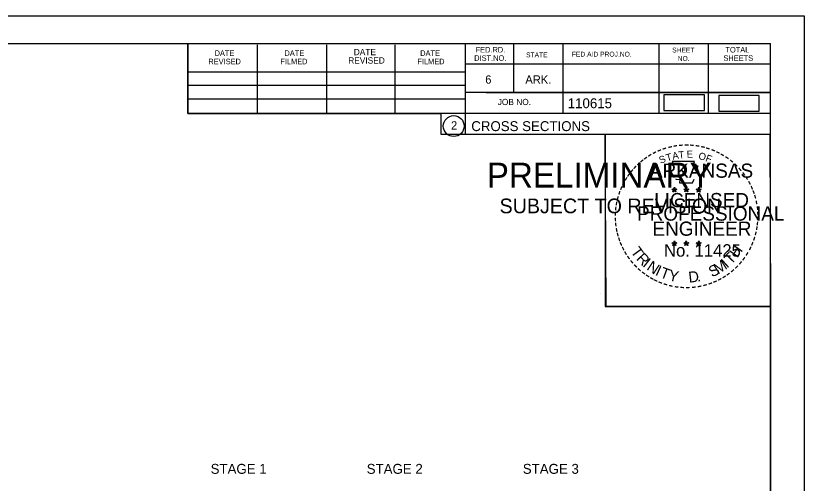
# Model space of a CAD drawing. Extents: x 1372132 to 1372465, y 380083 to 381790.
# Drawn here: x 1372353.7 to 1372464.9, y 381297.6 to 381363.5 of the extents above; entities that cross this region are included whole.
import ezdxf

# ---------------------------------------------------------------- set-up
doc = ezdxf.new("R2010")
doc.units = 0
for name, color, linetype in [('R_Axis Annot', 7, 'Continuous'), ('R_Border', 7, 'Continuous'), ('R_Border PE', 7, 'Continuous'), ('R_Border Prem', 7, 'Continuous'), ('R_Erosion', 7, 'Continuous'), ('R_No Plot', 7, 'Continuous')]:
    doc.layers.add(name, color=color, linetype=linetype)

msp = doc.modelspace()

# ---------------------------------------------------------------- linework, layer by layer
at = {"layer": 'R_Border'}
for p, q in [((1372144.01, 381359.62), (1372460.19, 381359.62)), ((1372377.93, 381349.74), (1372377.93, 381359.62)), ((1372387.79, 381349.74), (1372387.79, 381359.42)), ((1372397.55, 381349.74), (1372397.55, 381359.42)), ((1372407.23, 381349.74), (1372407.23, 381359.42)), ((1372417.09, 381359.62), (1372417.09, 381346.82)), ((1372423.93, 381359.62), (1372423.93, 381352.68)), ((1372430.87, 381359.62), (1372430.87, 381349.74)), ((1372444.45, 381359.62), (1372444.45, 381349.74)), ((1372451.39, 381359.62), (1372451.39, 381349.74)), ((1372460.19, 381154.16), (1372460.19, 381359.62)), ((1372460.19, 381356.68), (1372417.09, 381356.68)), ((1372460.19, 381356.7), (1372460.19, 381356.7)), ((1372377.93, 381355.6), (1372417.09, 381355.6)), ((1372377.93, 381353.74), (1372417.09, 381353.74)), ((1372460.19, 381352.68), (1372417.09, 381352.68)), ((1372420.05, 381352.68), (1372460.19, 381352.68)), ((1372377.93, 381349.74), (1372377.93, 381351.8)), ((1372377.93, 381351.8), (1372417.09, 381351.8)), ((1372460.19, 381349.74), (1372377.93, 381349.74)), ((1372417.09, 381346.82), (1372460.19, 381346.82))]:
    msp.add_line(p, q, dxfattribs=at)
msp.add_circle((1372415.48, 381347.96), 1.47, dxfattribs=at)
at = {"layer": 'R_Border PE'}
for p, q in [((1372446.28, 381339.08), (1372446.63, 381338.97)), ((1372446.28, 381339.08), (1372446.53, 381339.03)), ((1372446.28, 381339.08), (1372446.52, 381338.96)), ((1372446.41, 381338.67), (1372446.63, 381338.97)), ((1372446.41, 381338.67), (1372446.54, 381338.91)), ((1372446.41, 381338.67), (1372446.63, 381338.89)), ((1372446.63, 381339.33), (1372446.59, 381339.08)), ((1372446.63, 381338.97), (1372446.63, 381339.33)), ((1372446.63, 381339.33), (1372446.68, 381339.08)), ((1372446.98, 381339.08), (1372446.63, 381338.97)), ((1372446.84, 381338.67), (1372446.63, 381338.97)), ((1372446.84, 381338.67), (1372446.63, 381338.88)), ((1372446.98, 381339.08), (1372446.69, 381339.03)), ((1372446.84, 381338.67), (1372446.7, 381338.96)), ((1372446.98, 381339.08), (1372446.77, 381338.98)), ((1372447.95, 381339.08), (1372448.3, 381338.97)), ((1372447.95, 381339.08), (1372448.2, 381339.03)), ((1372447.95, 381339.08), (1372448.19, 381338.96)), ((1372448.08, 381338.67), (1372448.3, 381338.97)), ((1372448.08, 381338.67), (1372448.21, 381338.91)), ((1372448.08, 381338.67), (1372448.3, 381338.89)), ((1372448.3, 381339.33), (1372448.26, 381339.08)), ((1372448.3, 381338.97), (1372448.3, 381339.33)), ((1372448.3, 381339.33), (1372448.35, 381339.08)), ((1372448.65, 381339.08), (1372448.3, 381338.97)), ((1372448.51, 381338.67), (1372448.3, 381338.97)), ((1372448.51, 381338.67), (1372448.3, 381338.88)), ((1372448.65, 381339.08), (1372448.36, 381339.03)), ((1372448.51, 381338.67), (1372448.37, 381338.96)), ((1372448.65, 381339.08), (1372448.44, 381338.98)), ((1372449.71, 381339.07), (1372450.06, 381338.96)), ((1372449.71, 381339.07), (1372449.97, 381339.02)), ((1372449.71, 381339.07), (1372449.95, 381338.94)), ((1372449.85, 381338.66), (1372450.06, 381338.96)), ((1372449.85, 381338.66), (1372449.97, 381338.9)), ((1372449.85, 381338.66), (1372450.06, 381338.88)), ((1372450.06, 381339.32), (1372450.02, 381339.07)), ((1372450.06, 381338.96), (1372450.06, 381339.32)), ((1372450.06, 381339.32), (1372450.11, 381339.07)), ((1372450.41, 381339.07), (1372450.06, 381338.96)), ((1372450.28, 381338.66), (1372450.06, 381338.96)), ((1372450.28, 381338.66), (1372450.06, 381338.87)), ((1372450.41, 381339.07), (1372450.12, 381339.02)), ((1372450.28, 381338.66), (1372450.14, 381338.95)), ((1372450.41, 381339.07), (1372450.21, 381338.96)), ((1372446.28, 381331.51), (1372446.62, 381331.39)), ((1372446.28, 381331.51), (1372446.53, 381331.46)), ((1372446.28, 381331.51), (1372446.51, 381331.38)), ((1372446.41, 381331.1), (1372446.62, 381331.39)), ((1372446.41, 381331.1), (1372446.53, 381331.34)), ((1372446.41, 381331.1), (1372446.62, 381331.31)), ((1372446.62, 381331.76), (1372446.58, 381331.51)), ((1372446.62, 381331.39), (1372446.62, 381331.76)), ((1372446.62, 381331.76), (1372446.67, 381331.51)), ((1372446.97, 381331.51), (1372446.62, 381331.39)), ((1372446.84, 381331.1), (1372446.62, 381331.39)), ((1372446.84, 381331.1), (1372446.62, 381331.31)), ((1372446.97, 381331.51), (1372446.69, 381331.46)), ((1372446.84, 381331.1), (1372446.7, 381331.39)), ((1372446.97, 381331.51), (1372446.77, 381331.4)), ((1372447.94, 381331.51), (1372448.29, 381331.39)), ((1372447.94, 381331.51), (1372448.2, 381331.46)), ((1372447.94, 381331.51), (1372448.18, 381331.38)), ((1372448.08, 381331.1), (1372448.29, 381331.39)), ((1372448.08, 381331.1), (1372448.2, 381331.34)), ((1372448.08, 381331.1), (1372448.29, 381331.31)), ((1372448.29, 381331.76), (1372448.25, 381331.51)), ((1372448.29, 381331.39), (1372448.29, 381331.76)), ((1372448.29, 381331.76), (1372448.34, 381331.51)), ((1372448.64, 381331.51), (1372448.29, 381331.39)), ((1372448.51, 381331.1), (1372448.29, 381331.39)), ((1372448.51, 381331.1), (1372448.29, 381331.31)), ((1372448.64, 381331.51), (1372448.35, 381331.46)), ((1372448.51, 381331.1), (1372448.37, 381331.39)), ((1372448.64, 381331.51), (1372448.44, 381331.4)), ((1372449.71, 381331.5), (1372450.06, 381331.38)), ((1372449.71, 381331.5), (1372449.96, 381331.45)), ((1372449.71, 381331.5), (1372449.95, 381331.37)), ((1372449.84, 381331.09), (1372450.06, 381331.38)), ((1372449.84, 381331.09), (1372449.97, 381331.33)), ((1372449.84, 381331.09), (1372450.06, 381331.3)), ((1372450.06, 381331.75), (1372450.02, 381331.5)), ((1372450.06, 381331.38), (1372450.06, 381331.75)), ((1372450.06, 381331.75), (1372450.11, 381331.5)), ((1372450.41, 381331.5), (1372450.06, 381331.38)), ((1372450.27, 381331.09), (1372450.06, 381331.38)), ((1372450.27, 381331.09), (1372450.06, 381331.3)), ((1372450.41, 381331.5), (1372450.12, 381331.45)), ((1372450.27, 381331.09), (1372450.14, 381331.38)), ((1372450.41, 381331.5), (1372450.2, 381331.39))]:
    msp.add_line(p, q, dxfattribs=at)
for points in [[(1372446.32, 381342.96), (1372446.59, 381342.13)], [(1372449.83, 381342.03), (1372449.97, 381342.32), (1372449.29, 381342.29), (1372449.44, 381342.96), (1372446.32, 381342.96)], [(1372446.81, 381340.53), (1372446.81, 381340.45), (1372447.38, 381340.43), (1372447.32, 381339.95), (1372449.19, 381339.95), (1372449.39, 381340.49)], [(1372446.63, 381339.33), (1372446.84, 381338.67), (1372446.28, 381339.08), (1372446.98, 381339.08), (1372446.41, 381338.67), (1372446.63, 381339.33)], [(1372448.3, 381339.33), (1372448.51, 381338.67), (1372447.95, 381339.08), (1372448.65, 381339.08), (1372448.08, 381338.67), (1372448.3, 381339.33)], [(1372450.06, 381339.32), (1372450.28, 381338.66), (1372449.71, 381339.07), (1372450.41, 381339.07), (1372449.85, 381338.66), (1372450.06, 381339.32)], [(1372446.62, 381331.76), (1372446.84, 381331.1), (1372446.28, 381331.51), (1372446.97, 381331.51), (1372446.41, 381331.1), (1372446.62, 381331.76)], [(1372448.29, 381331.76), (1372448.51, 381331.1), (1372447.94, 381331.51), (1372448.64, 381331.51), (1372448.08, 381331.1), (1372448.29, 381331.76)], [(1372450.06, 381331.75), (1372450.27, 381331.09), (1372449.71, 381331.5), (1372450.41, 381331.5), (1372449.84, 381331.09), (1372450.06, 381331.75)]]:
    msp.add_lwpolyline(points, dxfattribs=at)
for centre, radius in [((1372446.63, 381338.97), 0.172), ((1372446.63, 381338.97), 0.145), ((1372446.63, 381338.97), 0.116), ((1372446.63, 381338.97), 0.0991), ((1372446.63, 381338.97), 0.0747), ((1372446.63, 381338.97), 0.0495), ((1372446.63, 381338.97), 0.0296), ((1372448.3, 381338.97), 0.172), ((1372448.3, 381338.97), 0.145), ((1372448.3, 381338.97), 0.116), ((1372448.3, 381338.97), 0.0991), ((1372448.3, 381338.97), 0.0747), ((1372448.3, 381338.97), 0.0495), ((1372448.3, 381338.97), 0.0296), ((1372450.06, 381338.95), 0.172), ((1372450.06, 381338.95), 0.145), ((1372450.06, 381338.95), 0.116), ((1372450.06, 381338.95), 0.0991), ((1372450.06, 381338.95), 0.0747), ((1372450.06, 381338.95), 0.0495), ((1372450.06, 381338.95), 0.0296), ((1372446.62, 381331.39), 0.172), ((1372446.62, 381331.39), 0.145), ((1372446.62, 381331.39), 0.116), ((1372446.62, 381331.39), 0.0991), ((1372446.62, 381331.39), 0.0747), ((1372446.62, 381331.39), 0.0495), ((1372446.62, 381331.39), 0.0296), ((1372448.29, 381331.39), 0.172), ((1372448.29, 381331.39), 0.145), ((1372448.29, 381331.39), 0.116), ((1372448.29, 381331.39), 0.0991), ((1372448.29, 381331.39), 0.0747), ((1372448.29, 381331.39), 0.0495), ((1372448.29, 381331.39), 0.0296), ((1372450.06, 381331.38), 0.172), ((1372450.06, 381331.38), 0.145), ((1372450.06, 381331.38), 0.116), ((1372450.06, 381331.38), 0.0991), ((1372450.06, 381331.38), 0.0747), ((1372450.06, 381331.38), 0.0495), ((1372450.06, 381331.38), 0.0296)]:
    msp.add_circle(centre, radius, dxfattribs=at)
at = {"layer": 'R_Erosion'}
for points in [[(1372445.13, 381350.17), (1372450.85, 381350.17), (1372450.85, 381352.36), (1372445.13, 381352.36)], [(1372452.88, 381350.08), (1372458.59, 381350.08), (1372458.59, 381352.27), (1372452.88, 381352.27)]]:
    msp.add_lwpolyline(points, close=True, dxfattribs=at)
at = {"layer": 'R_No Plot'}
for p, q in [((1372131.61, 381363.52), (1372464.95, 381363.52)), ((1372436.23, 381324.37), (1372436.23, 381324.37))]:
    msp.add_line(p, q, dxfattribs=at)
for points in [[(1372131.61, 381363.52), (1372464.95, 381363.52), (1372464.95, 381150.18), (1372131.61, 381150.18)], [(1372377.93, 381359.62), (1372377.93, 381349.74), (1372413.67, 381349.74), (1372413.67, 381346.82), (1372436.87, 381346.82), (1372436.87, 381322.49), (1372460.19, 381322.49), (1372460.19, 381154.16), (1372144.01, 381154.16), (1372144.01, 381359.62)], [(1372436.87, 381346.82), (1372460.07, 381346.82), (1372460.19, 381322.49), (1372436.99, 381322.49)]]:
    msp.add_lwpolyline(points, close=True, dxfattribs=at)

# ---------------------------------------------------------------- texts
at = {"layer": 'R_Axis Annot'}
for s, p in [('STAGE 1', (1372381.17, 381298.91)), ('STAGE 2', (1372403.2, 381298.91)), ('STAGE 3', (1372425.23, 381298.91))]:
    msp.add_text(s, height=1.4, dxfattribs=at).set_placement(p)
at = {"layer": 'R_Border'}
for s, height, p in [('DATE', 0.879, (1372401.37, 381357.96)), ('FED.RD.', 0.782, (1372418.57, 381358.34)), ('SHEET', 0.684, (1372446.31, 381358.34)), ('TOTAL', 0.782, (1372453.83, 381358.34)), ('DATE', 0.782, (1372381.73, 381357.86)), ('DATE', 0.782, (1372391.59, 381357.86)), ('DATE', 0.782, (1372410.75, 381357.86)), ('DIST.NO.', 0.782, (1372418.37, 381357.16)), ('STATE', 0.684, (1372425.69, 381357.66)), ('FED.AID PROJ.NO.', 0.684, (1372432.15, 381357.76)), ('NO.', 0.684, (1372447.09, 381357.16)), ('SHEETS', 0.782, (1372453.55, 381357.16)), ('REVISED', 0.782, (1372380.85, 381356.68)), ('FILMED', 0.782, (1372391.01, 381356.68)), ('REVISED', 0.879, (1372400.59, 381356.78)), ('FILMED', 0.782, (1372410.35, 381356.68)), ('6', 1.17, (1372419.93, 381353.94)), ('ARK.', 1.172, (1372425.59, 381353.94)), ('JOB NO.', 0.879, (1372421.69, 381350.92)), ('110615', 1.4, (1372431.57, 381350.48)), ('2', 1.17, (1372415.1, 381347.47)), ('CROSS SECTIONS', 1.4, (1372417.96, 381347.25))]:
    msp.add_text(s, height=height, rotation=360, dxfattribs=at).set_placement(p)
at = {"layer": 'R_Border PE'}
for s, height, rotation, p in [('-', 1.6, 28.7918, (1372443.8, 381343.5)), ('-', 1.6, 24.3072, (1372444.43, 381343.81)), ('-', 1.6, 19.1761, (1372445.07, 381344.08)), ('-', 1.6, 13.6301, (1372445.82, 381344.32)), ('-', 1.6, 10.2193, (1372446.5, 381344.49)), ('T', 1, 6.0228, (1372447.26, 381343.38)), ('-', 1.6, 5.8968, (1372447.23, 381344.6)), ('-', 1.6, 0.1862, (1372448, 381344.67)), ('E', 1, 0.8323, (1372448.37, 381343.49)), ('-', 1.6, 357.743, (1372448.72, 381344.66)), ('-', 1.6, 352.1617, (1372449.46, 381344.6)), ('-', 1.6, 347.2049, (1372450.18, 381344.49)), ('-', 1.6, 342.3362, (1372450.82, 381344.33)), ('-', 1.6, 337.8551, (1372451.55, 381344.11)), ('-', 1.6, 334.1211, (1372452.18, 381343.84)), ('-', 1.6, 38.9507, (1372442.15, 381342.35)), ('-', 1.6, 36.2317, (1372442.63, 381342.73)), ('-', 1.6, 34.0636, (1372443.2, 381343.13)), ('S', 1, 21.594, (1372444.68, 381342.63)), ('T', 1, 16.4036, (1372445.59, 381342.97)), ('A', 1, 11.2132, (1372446.42, 381343.22)), ('O', 1, 350.4515, (1372449.97, 381343.28)), ('F', 1, 340.0707, (1372450.93, 381343.05)), ('-', 1.6, 329.6409, (1372452.76, 381343.55)), ('-', 1.6, 325.8627, (1372453.41, 381343.19)), ('-', 1.6, 320.5297, (1372454.02, 381342.77)), ('-', 1.6, 48.423, (1372441.27, 381341.46)), ('-', 1.6, 42.9622, (1372441.72, 381341.94)), ('ARKANSAS', 2, 360, (1372443.17, 381340.67)), ('-', 1.6, 315.5786, (1372454.62, 381342.28)), ('-', 1.6, 54.2325, (1372440.45, 381340.41)), ('-', 1.6, 50.6142, (1372440.87, 381340.97)), ('-', 1.6, 309.8797, (1372455.18, 381341.73)), ('-', 1.6, 306.6522, (1372455.71, 381341.13)), ('-', 1.6, 62.8713, (1372439.82, 381339.27)), ('-', 1.6, 58.0706, (1372440.13, 381339.88)), ('-', 1.4, 303.6753, (1372456.2, 381340.56)), ('-', 1.6, 299.6684, (1372456.51, 381339.95)), ('-', 1.6, 72.3945, (1372439.34, 381338.02)), ('-', 1.6, 67.7743, (1372439.56, 381338.65)), ('DWB', 0.01, 360, (1372446.62, 381338.96)), ('DWB', 0.01, 360, (1372448.29, 381338.96)), ('DWB', 0.01, 360, (1372450.05, 381338.95)), ('-', 1.6, 294.6628, (1372456.84, 381339.34)), ('-', 1.6, 290.5728, (1372457.1, 381338.76)), ('-', 1.6, 75.461, (1372439.14, 381337.31)), ('LICENSED', 2, 360, (1372443.77, 381336.52)), ('-', 1.6, 285.1233, (1372457.33, 381338.18)), ('-', 1.6, 85.1863, (1372438.93, 381335.91)), ('-', 1.6, 81.2013, (1372439.01, 381336.6)), ('PROFESSIONAL', 2, 360, (1372441.35, 381334.62)), ('-', 1.6, 280.5493, (1372457.53, 381337.44)), ('-', 1.6, 276.5962, (1372457.69, 381336.67)), ('-', 1.6, 89.0622, (1372438.91, 381335.21)), ('-', 1.6, 274.3301, (1372457.75, 381335.95)), ('-', 1.6, 94.1959, (1372438.94, 381334.48)), ('-', 1.6, 98.9479, (1372439.01, 381333.81)), ('ENGINEER', 2, 360, (1372443.53, 381332.49)), ('-', 1.6, 263.5172, (1372457.77, 381334.65)), ('-', 1.6, 269.9407, (1372457.79, 381335.32)), ('-', 1.6, 101.7149, (1372439.15, 381333.08)), ('-', 1.6, 260.9953, (1372457.7, 381334)), ('-', 1.6, 105.4578, (1372439.31, 381332.49)), ('-', 1.6, 109.0874, (1372439.53, 381331.85)), ('-', 1.6, 252.8681, (1372457.4, 381332.6)), ('-', 1.6, 255.7626, (1372457.59, 381333.32)), ('-', 1.6, 114.0643, (1372439.78, 381331.26)), ('T', 1.54, 306.0406, (1372440.38, 381330.23)), ('No. 11425', 1.757, 360, (1372445.16, 381329.54)), ('DWB', 0.01, 360, (1372446.61, 381331.39)), ('DWB', 0.01, 360, (1372448.28, 381331.39)), ('DWB', 0.01, 360, (1372450.05, 381331.38)), ('H', 1.54, 54.6088, (1372455.5, 381329.27)), ('-', 1.6, 247.8887, (1372457.18, 381331.93)), ('-', 1.6, 115.7289, (1372440.09, 381330.64)), ('-', 1.6, 120.4471, (1372440.44, 381330.05)), ('R', 1.54, 314.005, (1372441.15, 381329.18)), ('T', 1.54, 46.6444, (1372454.61, 381328.33)), ('-', 1.6, 239.0712, (1372456.53, 381330.55)), ('-', 1.6, 244.6197, (1372456.92, 381331.3)), ('-', 1.6, 125.8934, (1372440.85, 381329.49)), ('-', 1.6, 130.7181, (1372441.31, 381328.94)), ('I', 1.54, 321.9694, (1372442.05, 381328.25)), ('N', 1.54, 326.5002, (1372442.61, 381327.78)), ('M', 1.54, 32.6563, (1372452.77, 381327)), ('I', 1.54, 42.1136, (1372454.05, 381327.85)), ('-', 1.6, 231.2538, (1372455.69, 381329.33)), ('-', 1.6, 233.8452, (1372456.12, 381329.89)), ('-', 1.6, 134.2238, (1372441.82, 381328.4)), ('-', 1.6, 138.9338, (1372442.35, 381327.93)), ('I', 1.54, 335.3603, (1372443.82, 381326.99)), ('T', 1.54, 339.8912, (1372444.48, 381326.67)), ('Y', 1.54, 347.8556, (1372445.7, 381326.22)), ('S', 1.54, 26.9312, (1372451.93, 381326.59)), ('-', 1.6, 221.0851, (1372454.69, 381328.25)), ('-', 1.6, 225.7653, (1372455.21, 381328.76)), ('-', 1.6, 144.6463, (1372442.91, 381327.53)), ('-', 1.6, 148.0898, (1372443.47, 381327.16)), ('-', 1.6, 151.5704, (1372444.05, 381326.83)), ('D', 1.54, 6.3969, (1372448.69, 381325.86)), ('-', 1.6, 212.2491, (1372453.61, 381327.4)), ('-', 1.6, 215.7363, (1372454.14, 381327.78)), ('-', 1.6, 154.6002, (1372444.57, 381326.58)), ('-', 1.6, 158.5612, (1372445.19, 381326.33)), ('-', 1.6, 162.7983, (1372445.88, 381326.12)), ('-', 1.6, 167.5555, (1372446.59, 381325.95)), ('-', 1.6, 191.2858, (1372450.4, 381326.02)), ('.', 1.54, 13.7642, (1372449.88, 381325.99)), ('-', 1.6, 195.4743, (1372451.13, 381326.22)), ('-', 1.6, 200.7184, (1372451.81, 381326.46)), ('-', 1.6, 204.2516, (1372452.43, 381326.73)), ('-', 1.6, 207.3568, (1372453.05, 381327.05)), ('-', 1.6, 173.1155, (1372447.37, 381325.84)), ('-', 1.6, 176.5183, (1372448.11, 381325.79)), ('-', 1.6, 181.5918, (1372448.86, 381325.81)), ('-', 1.6, 185.8167, (1372449.67, 381325.88))]:
    msp.add_text(s, height=height, rotation=rotation, dxfattribs=at).set_placement(p)
at = {"layer": 'R_Border Prem'}
for s, height, p in [('PRELIMINARY', 3.5, (1372420.15, 381339.29)), ('DWB', 0.01, (1372420.89, 381341.14)), ('SUBJECT TO REVISION', 2.0751, (1372421.95, 381335.66))]:
    msp.add_text(s, height=height, rotation=360, dxfattribs=at).set_placement(p)

doc.saveas('drawing.dxf')
